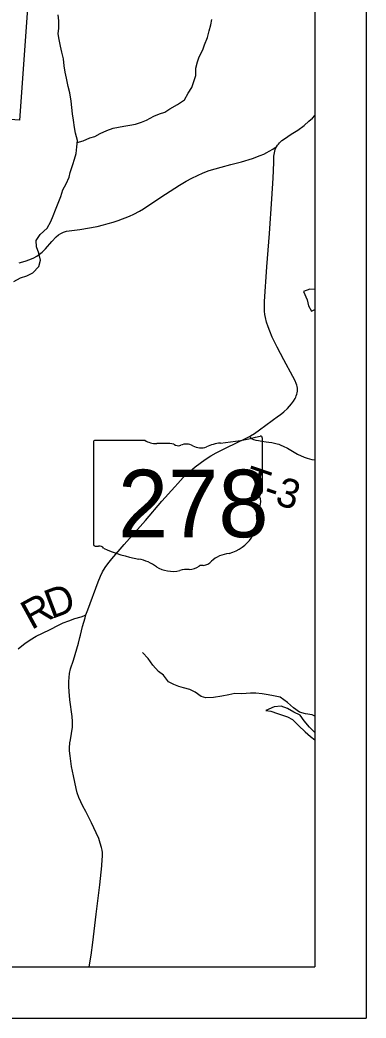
# Model space of a CAD drawing. Extents: x 0 to 34, y 0 to 22.
# Drawn here: x 8.324 to 9, y 14 to 15.952 of the extents above; entities that cross this region are included whole.
import ezdxf

# ---------------------------------------------------------------- set-up
doc = ezdxf.new("R2010")
doc.units = 0
for name, color, linetype in [('GM_X_Corporation', 7, 'Continuous'), ('GM_X_County_Road', 7, 'Continuous'), ('GM_X_Minor_Lake', 7, 'Continuous'), ('GM_X_Minor_River', 7, 'Continuous'), ('GM_X_State_Location', 7, 'Continuous'), ('GM_X_State_Route', 7, 'Continuous'), ('GM_X_State_Shield', 7, 'Continuous'), ('GM_X_Township_Road', 7, 'Continuous'), ('GM_X_Township_Road_Text', 7, 'Continuous'), ('SH_Data', 7, 'Continuous')]:
    doc.layers.add(name, color=color, linetype=linetype)

msp = doc.modelspace()

# ---------------------------------------------------------------- linework, layer by layer
at = {"layer": 'GM_X_Corporation'}
msp.add_lwpolyline([(8.3529, 16.1745), (8.3234, 15.756), (7.3238, 15.8259), (7.3548, 16.2394)], close=True, dxfattribs=at)
at = {"layer": 'GM_X_County_Road'}
msp.add_lwpolyline([(8.3225, 15.4768), (8.3341, 15.4799), (8.3431, 15.4831), (8.3511, 15.4866), (8.3573, 15.49), (8.3625, 15.4937), (8.3674, 15.4977), (8.3741, 15.5042), (8.3864, 15.5185), (8.3948, 15.5275), (8.3994, 15.5315), (8.4037, 15.5342), (8.4088, 15.5366), (8.415, 15.5384), (8.42, 15.5394), (8.4256, 15.5401), (8.4409, 15.5421), (8.475, 15.548), (8.4873, 15.5508), (8.4963, 15.5533), (8.506, 15.5562), (8.5157, 15.5594), (8.5378, 15.5679), (8.5465, 15.5718), (8.5576, 15.5775), (8.5656, 15.5824), (8.5991, 15.6048), (8.6355, 15.6284), (8.6487, 15.6365), (8.6595, 15.6424), (8.6706, 15.6478), (8.682, 15.6526), (8.6935, 15.657), (8.7053, 15.6608), (8.7173, 15.6641), (8.7362, 15.6687), (8.7566, 15.6742), (8.7782, 15.6808), (8.7935, 15.6863), (8.8001, 15.6893), (8.8064, 15.6926), (8.8109, 15.6951), (8.8177, 15.6991), (8.8227, 15.7022), (8.8252, 15.7038)], dxfattribs=at)
at = {"layer": 'GM_X_Minor_Lake'}
for p, q in [((8.8903, 15.4254), (8.8778, 15.4204)), ((8.8778, 15.4204), (8.8852, 15.4045)), ((8.9, 15.4243), (8.8903, 15.4254)), ((8.8852, 15.4045), (8.8875, 15.3924)), ((8.8875, 15.3924), (8.8933, 15.3823)), ((8.8933, 15.3823), (8.9, 15.3852)), ((8.8206, 14.6085), (8.804, 14.6012)), ((8.804, 14.6012), (8.8142, 14.5998)), ((8.8142, 14.5998), (8.8268, 14.5957)), ((8.8342, 14.6098), (8.8206, 14.6085)), ((8.8467, 14.605), (8.8342, 14.6098)), ((8.8589, 14.5983), (8.8467, 14.605)), ((8.8714, 14.5923), (8.8589, 14.5983)), ((8.8268, 14.5957), (8.837, 14.592)), ((8.837, 14.592), (8.8469, 14.5891)), ((8.8469, 14.5891), (8.8564, 14.5835)), ((8.8564, 14.5835), (8.8678, 14.5718)), ((8.8791, 14.581), (8.8714, 14.5923)), ((8.8894, 14.5686), (8.8791, 14.581)), ((8.8678, 14.5718), (8.8812, 14.5598)), ((8.8812, 14.5598), (8.8915, 14.5505)), ((8.8997, 14.5593), (8.8894, 14.5686)), ((8.9, 14.5591), (8.8997, 14.5593)), ((8.8915, 14.5505), (8.9, 14.5439))]:
    msp.add_line(p, q, dxfattribs=at)
at = {"layer": 'GM_X_Minor_River'}
for p, q in [((8.697, 15.9424), (8.6988, 15.9523)), ((8.6904, 15.917), (8.6937, 15.9303)), ((8.6937, 15.9303), (8.697, 15.9424)), ((8.6848, 15.9033), (8.6904, 15.917)), ((8.6741, 15.8797), (8.6812, 15.8934)), ((8.6812, 15.8934), (8.6848, 15.9033)), ((8.6678, 15.8573), (8.6708, 15.8698)), ((8.6708, 15.8698), (8.6741, 15.8797)), ((8.6676, 15.8433), (8.6678, 15.8573)), ((8.6598, 15.8197), (8.6639, 15.8315)), ((8.6639, 15.8315), (8.6676, 15.8433)), ((8.6457, 15.7957), (8.6524, 15.8086)), ((8.6524, 15.8086), (8.6598, 15.8197)), ((8.6321, 15.7865), (8.6457, 15.7957)), ((8.5963, 15.7683), (8.6069, 15.7715)), ((8.6069, 15.7715), (8.6171, 15.778)), ((8.6171, 15.778), (8.6321, 15.7865)), ((8.55, 15.7478), (8.5617, 15.7517)), ((8.5617, 15.7517), (8.5715, 15.756)), ((8.5715, 15.756), (8.5858, 15.7633)), ((8.5858, 15.7633), (8.5963, 15.7683)), ((8.4805, 15.7298), (8.4937, 15.7356)), ((8.4937, 15.7356), (8.5062, 15.7399)), ((8.5062, 15.7399), (8.5164, 15.7422)), ((8.5164, 15.7422), (8.5269, 15.7442)), ((8.5269, 15.7442), (8.5386, 15.7462)), ((8.5386, 15.7462), (8.55, 15.7478)), ((8.4361, 15.7122), (8.4477, 15.7154)), ((8.4477, 15.7154), (8.4605, 15.7209)), ((8.4605, 15.7209), (8.4704, 15.724)), ((8.4704, 15.724), (8.4805, 15.7298)), ((8.5742, 14.7033), (8.5635, 14.7146)), ((8.5838, 14.6901), (8.5742, 14.7033)), ((8.5945, 14.6777), (8.5838, 14.6901)), ((8.6044, 14.6702), (8.5945, 14.6777)), ((8.6143, 14.6574), (8.6044, 14.6702)), ((8.6246, 14.6522), (8.6143, 14.6574)), ((8.6341, 14.6482), (8.6246, 14.6522)), ((8.6436, 14.6456), (8.6341, 14.6482)), ((8.6557, 14.6427), (8.6436, 14.6456)), ((8.666, 14.6375), (8.6557, 14.6427)), ((8.6778, 14.6285), (8.666, 14.6375)), ((8.6873, 14.6263), (8.6778, 14.6285)), ((8.7024, 14.6268), (8.6873, 14.6263)), ((8.7182, 14.6296), (8.7024, 14.6268)), ((8.7322, 14.632), (8.7182, 14.6296)), ((8.7436, 14.6344), (8.7322, 14.632)), ((8.7572, 14.6341), (8.7436, 14.6344)), ((8.7746, 14.6354), (8.7572, 14.6341)), ((8.7848, 14.6355), (8.7746, 14.6354)), ((8.7973, 14.6337), (8.7848, 14.6355)), ((8.8087, 14.6319), (8.7973, 14.6337)), ((8.8193, 14.6301), (8.8087, 14.6319)), ((8.8322, 14.6272), (8.8193, 14.6301)), ((8.8466, 14.6167), (8.8322, 14.6272)), ((8.8581, 14.6066), (8.8466, 14.6167)), ((8.8702, 14.598), (8.8581, 14.6066)), ((8.882, 14.5947), (8.8702, 14.598)), ((8.8949, 14.5926), (8.882, 14.5947)), ((8.9, 14.59), (8.8949, 14.5926))]:
    msp.add_line(p, q, dxfattribs=at)
for points in [[(8.3988, 15.5934), (8.4036, 15.6067), (8.4081, 15.6192), (8.4144, 15.631), (8.42, 15.644), (8.4222, 15.6535), (8.4273, 15.669), (8.4306, 15.6793), (8.4336, 15.6903), (8.4353, 15.7036), (8.4364, 15.7161), (8.4325, 15.7305), (8.4309, 15.7414), (8.4285, 15.7554), (8.4268, 15.7683), (8.4256, 15.7804), (8.4244, 15.7929), (8.4216, 15.8088), (8.4181, 15.8213), (8.4149, 15.8375), (8.4121, 15.8496), (8.4105, 15.8621), (8.4089, 15.8758), (8.4057, 15.8886), (8.4034, 15.9003), (8.4006, 15.9136), (8.399, 15.9246), (8.4, 15.9356), (8.4003, 15.9496), (8.3987, 15.9617)], [(8.312, 15.4402), (8.3252, 15.4476), (8.3376, 15.4515), (8.3493, 15.4569), (8.361, 15.4695), (8.3642, 15.482), (8.3611, 15.4956), (8.3561, 15.5077), (8.356, 15.5202), (8.3634, 15.5324), (8.3769, 15.5447), (8.3844, 15.5576), (8.3892, 15.5683), (8.3933, 15.5801), (8.3988, 15.5934)]]:
    msp.add_lwpolyline(points, dxfattribs=at)
at = {"layer": 'GM_X_State_Route'}
msp.add_lwpolyline([(8.4593, 14.1), (8.463, 14.1231), (8.4662, 14.1478), (8.4728, 14.2033), (8.4804, 14.2604), (8.4837, 14.2976), (8.4848, 14.3098), (8.4853, 14.3158), (8.4854, 14.32), (8.4851, 14.3237), (8.4846, 14.3283), (8.4836, 14.3333), (8.481, 14.3422), (8.4778, 14.3509), (8.4729, 14.3622), (8.4637, 14.3818), (8.4527, 14.4037), (8.4468, 14.4141), (8.4428, 14.4225), (8.4392, 14.4312), (8.4361, 14.4401), (8.4338, 14.4491), (8.4284, 14.4734), (8.425, 14.4917), (8.4219, 14.513), (8.4211, 14.5224), (8.421, 14.5286), (8.4217, 14.5379), (8.4225, 14.5441), (8.4246, 14.5562), (8.4256, 14.5609), (8.4266, 14.5682), (8.427, 14.5746), (8.427, 14.5791), (8.427, 14.5797), (8.4261, 14.5896), (8.4216, 14.6219), (8.4199, 14.6388), (8.4194, 14.648), (8.4194, 14.658), (8.4204, 14.6657), (8.4211, 14.6737), (8.4228, 14.6826), (8.4286, 14.6996), (8.4383, 14.7329), (8.4412, 14.7444), (8.4423, 14.7486), (8.4465, 14.7653), (8.4514, 14.7826), (8.453, 14.7883), (8.4569, 14.7983), (8.4766, 14.8527), (8.4815, 14.8642), (8.4856, 14.8726), (8.4903, 14.8807), (8.4957, 14.8884), (8.5036, 14.8981), (8.5278, 14.9262), (8.5691, 14.9728), (8.6014, 15.0106), (8.6263, 15.0387), (8.6323, 15.0455), (8.643, 15.0568), (8.6519, 15.0655), (8.6661, 15.0775), (8.6758, 15.0852), (8.686, 15.0924), (8.6966, 15.099), (8.7075, 15.1051), (8.7269, 15.1149), (8.7661, 15.1338), (8.7721, 15.137), (8.7742, 15.1382), (8.7821, 15.143), (8.7922, 15.1502), (8.8293, 15.1774), (8.8325, 15.1797), (8.8397, 15.1856), (8.8464, 15.1919), (8.8507, 15.1964), (8.8546, 15.201), (8.8582, 15.206), (8.8613, 15.2113), (8.8626, 15.214), (8.8638, 15.2168), (8.8647, 15.2197), (8.8654, 15.2226), (8.8659, 15.2256), (8.866, 15.2286), (8.8659, 15.2316), (8.8655, 15.2346), (8.8648, 15.2376), (8.8638, 15.2405), (8.8615, 15.2461), (8.8572, 15.2543), (8.8393, 15.287), (8.8265, 15.3119), (8.8169, 15.3315), (8.8119, 15.3429), (8.8087, 15.3516), (8.8058, 15.3606), (8.8035, 15.3697), (8.8024, 15.3758), (8.8016, 15.3821), (8.8015, 15.3877), (8.8016, 15.3939), (8.802, 15.4008), (8.8064, 15.469), (8.8115, 15.5338), (8.8158, 15.602), (8.8186, 15.6423), (8.8198, 15.6732), (8.8202, 15.6856), (8.821, 15.6919), (8.8216, 15.695), (8.8226, 15.698), (8.8237, 15.701), (8.8252, 15.7038), (8.8269, 15.7065), (8.8289, 15.709), (8.8311, 15.7114), (8.8357, 15.7156), (8.8406, 15.7194), (8.8536, 15.728), (8.8666, 15.7363), (8.879, 15.7451), (8.8885, 15.7534), (8.8954, 15.7597), (8.9, 15.7646)], dxfattribs=at)
at = {"layer": 'GM_X_State_Shield'}
for p, q in [((8.4679, 15.1262), (8.4679, 14.9261)), ((8.5677, 15.1296), (8.4711, 15.1296)), ((8.7975, 15.0299), (8.7975, 15.1346)), ((8.7975, 15.0299), (8.7975, 15.0299))]:
    msp.add_line(p, q, dxfattribs=at)
for centre, major_axis, start_param, end_param in [((8.4717, 15.1266), (0.00382, 0), 1.712693, 3.28349), ((8.5907, 15.1529), (0.037, 0), 4.042523, 4.731795), ((8.6801, 15.4025), (0.3495, 0), 4.814394, 5.042369), ((8.7938, 15.135), (0.00367, 0), 6.141152, 7.989035), ((8.6029, 15.0173), (0.133, 0), 1.404758, 1.657858), ((8.6331, 15.1276), (0.0107, 0), 3.836095, 5.185415), ((8.6488, 15.1045), (0.0222, 0), 0.950623, 2.079405), ((8.6775, 15.1362), (0.0267, 0), 4.081561, 5.145723), ((8.7247, 15.0685), (0.0703, 0), 1.699011, 2.107814), ((8.7936, 15.0295), (0.00393, 0), 5.05454, 6.418171), ((8.7966, 15.0222), (0.00568, 0), 1.883978, 3.671073), ((8.7605, 15.009), (0.0341, 0), 5.934695, 6.695948), ((8.8106, 14.9861), (0.0248, 0), 2.387724, 3.262537), ((8.6997, 14.9728), (0.0874, 0), 5.101752, 6.440018), ((8.4717, 14.9256), (0.00385, 0), 3.00124, 4.508301), ((8.4723, 14.9461), (0.0294, 0), 4.665946, 4.897461), ((8.4783, 14.9145), (0.0106, 0), 0.519207, 1.627899), ((8.6121, 15.0943), (0.2524, 0), 4.195997, 4.488961), ((8.5369, 14.8362), (0.079, 0), 0.823519, 1.323587), ((8.6759, 14.9067), (0.0282, 0), 4.937069, 5.64225), ((8.7365, 14.8699), (0.0479, 0), 1.647645, 2.488434), ((8.6223, 14.9135), (0.0501, 0), 4.026481, 4.996735), ((8.6513, 14.8443), (0.0412, 0), 1.495662, 1.94098), ((8.6549, 14.8985), (0.0267, 0), 4.691044, 5.507374), ((8.6791, 14.8792), (0.00752, 0), 1.147584, 2.315152)]:
    msp.add_ellipse(centre, major_axis=major_axis, ratio=0.8, start_param=start_param, end_param=end_param, dxfattribs=at)
at = {"layer": 'GM_X_Township_Road'}
for points in [[(8.7721, 15.137), (8.7734, 15.1357), (8.7754, 15.1337), (8.7771, 15.1325), (8.7804, 15.1312), (8.7848, 15.1302), (8.7899, 15.1292), (8.7968, 15.1281), (8.8049, 15.1269), (8.8104, 15.126), (8.8159, 15.1251), (8.8211, 15.1242), (8.8267, 15.123), (8.83, 15.1221), (8.8337, 15.1205), (8.8382, 15.1184), (8.8466, 15.1142), (8.8663, 15.1028), (8.8791, 15.0966), (8.8849, 15.0947), (8.8939, 15.0924), (8.9, 15.0914)], [(8.3207, 14.7221), (8.3274, 14.7278), (8.3333, 14.7323), (8.3437, 14.7394), (8.3559, 14.7464), (8.3681, 14.7526), (8.3828, 14.7598), (8.3993, 14.7681), (8.4085, 14.7725), (8.4196, 14.777), (8.4315, 14.7813), (8.4434, 14.7847), (8.4486, 14.7864), (8.453, 14.7883)]]:
    msp.add_lwpolyline(points, dxfattribs=at)
at = {"layer": 'SH_Data'}
for p, q in [((9, 21), (9, 14)), ((8.9, 20.9), (8.9, 14.1)), ((2.1, 14.1), (8.9, 14.1)), ((2, 14), (9, 14))]:
    msp.add_line(p, q, dxfattribs=at)

# ---------------------------------------------------------------- texts
at = {"layer": 'GM_X_State_Location'}
for s in ['s', 'r']:
    msp.add_text(s, height=0.000189, dxfattribs=at).set_placement((8.629, 15.0128))
msp.add_text('278', height=0.000189, rotation=0, dxfattribs=at).set_placement((8.5621, 14.999))
at = {"layer": 'GM_X_State_Shield'}
msp.add_text('278', height=0.13184, dxfattribs=at).set_placement((8.5155, 14.9402))
at = {"layer": 'GM_X_Township_Road_Text'}
for s, rotation, p in [('T', 341.0894, (8.756, 15.0271)), ('3', 343.0238, (8.8203, 15.0053)), ('-', 341.3999, (8.7965, 15.0133)), ('D', 20.5654, (8.3856, 14.7798)), ('R', 28.6425, (8.3465, 14.7583))]:
    msp.add_text(s, height=0.0568, rotation=rotation, dxfattribs=at).set_placement(p)

doc.saveas('drawing.dxf')
